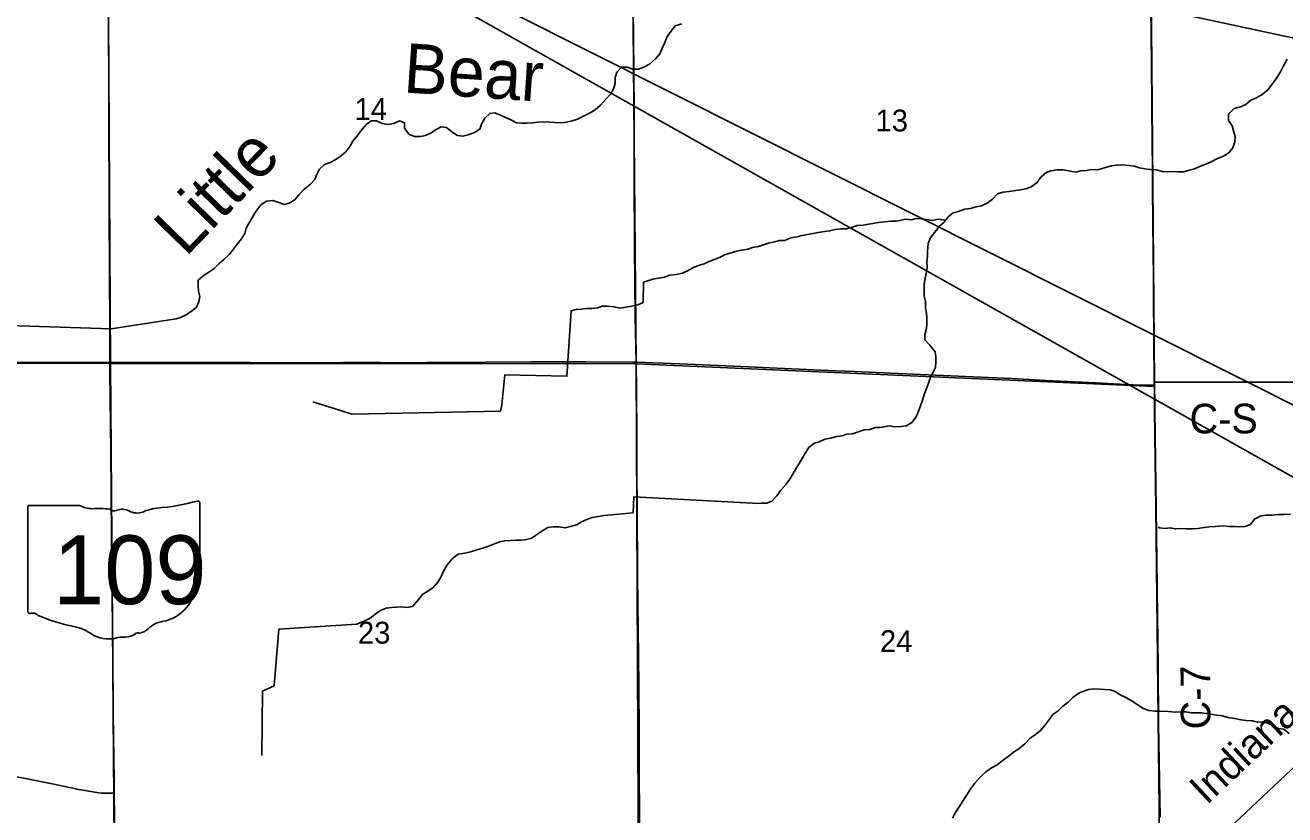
# Model space of a CAD drawing. Extents: x 0 to 34, y 0 to 22.
# Drawn here: x 5.327 to 7.743, y 17.786 to 19.3 of the extents above; entities that cross this region are included whole.
import ezdxf

# ---------------------------------------------------------------- set-up
doc = ezdxf.new("R2010")
doc.units = 0
for name, color, linetype in [('Default', 7, 'Continuous'), ('GM_X_County_Road', 7, 'Continuous'), ('GM_X_County_Road_Text', 7, 'Continuous'), ('GM_X_Minor_River', 7, 'Continuous'), ('GM_X_Minor_River_Text', 7, 'Continuous'), ('GM_X_Rail_Line', 7, 'Continuous'), ('GM_X_Rail_Line_Text', 7, 'Continuous'), ('GM_X_Section', 7, 'Continuous'), ('GM_X_Section_Text', 7, 'Continuous'), ('GM_X_State_Location', 7, 'Continuous'), ('GM_X_State_Route', 7, 'Continuous'), ('GM_X_State_Shield', 7, 'Continuous'), ('GM_X_Township_Road', 7, 'Continuous'), ('SH_Text', 7, 'Continuous')]:
    doc.layers.add(name, color=color, linetype=linetype)

msp = doc.modelspace()

# ---------------------------------------------------------------- linework, layer by layer
at = {"layer": 'Default'}
for points in [[(7.5032, 17.7822), (7.5006, 17.9615), (7.4999, 18.0704), (7.4982, 18.1668), (7.4976, 18.2228), (7.4963, 18.3254), (7.4931, 18.5618), (7.493, 18.5805), (7.4926, 18.6053), (7.4924, 18.6103), (7.4924, 18.6163), (7.4914, 18.6987), (7.4908, 18.7826), (7.4907, 18.8137), (7.4895, 18.9226), (7.4892, 18.9879), (7.4888, 19.0283), (7.4883, 19.0719), (7.487, 19.2243), (7.4864, 19.2834), (7.4852, 19.3829)], [(7.4852, 19.3829), (7.4864, 19.2834), (7.487, 19.2243), (7.4883, 19.0719), (7.4888, 19.0283), (7.4892, 18.9879), (7.4895, 18.9226), (7.4907, 18.8137), (7.4908, 18.7826), (7.4914, 18.6987), (7.4924, 18.6163), (7.4924, 18.6103), (7.4926, 18.6053), (7.493, 18.5805), (7.4931, 18.5618), (7.4963, 18.3254), (7.4976, 18.2228), (7.4982, 18.1668), (7.4999, 18.0704), (7.5006, 17.9615), (7.5032, 17.7822)]]:
    msp.add_lwpolyline(points, dxfattribs=at)
at = {"layer": 'GM_X_County_Road'}
msp.add_line((7.4927, 18.6097), (7.4927, 18.6157), dxfattribs=at)
for points in [[(7.4927, 18.6157), (7.4917, 18.6981), (7.4911, 18.7821), (7.4909, 18.8132), (7.4898, 18.922), (7.4894, 18.9873), (7.4891, 19.0278), (7.4886, 19.0713), (7.4872, 19.2237), (7.4867, 19.2828), (7.4854, 19.3824), (7.4845, 19.4477), (7.484, 19.5099), (7.483, 19.5845), (7.4829, 19.602)], [(4.4843, 18.6526), (4.5342, 18.653), (4.7114, 18.6535), (4.9663, 18.6544), (5.1249, 18.6544), (5.1746, 18.6543), (5.2305, 18.654), (5.3611, 18.6537), (5.4896, 18.6535)], [(5.4896, 18.6535), (5.4979, 18.6535), (5.6222, 18.6535), (5.759, 18.6531), (5.8367, 18.6529), (5.9362, 18.6532), (6.0077, 18.6532), (6.0823, 18.653), (6.0978, 18.6531), (6.1258, 18.6536), (6.2968, 18.6549), (6.4025, 18.6548), (6.4927, 18.6543), (6.4986, 18.6541)], [(6.4986, 18.6541), (6.5828, 18.6511), (6.6853, 18.6465), (6.8809, 18.6376), (6.9182, 18.636), (6.9865, 18.633), (7.1449, 18.626), (7.2194, 18.6225), (7.2846, 18.6191), (7.3809, 18.6143), (7.415, 18.6126), (7.4647, 18.6102), (7.4927, 18.6097)], [(7.4927, 18.6157), (7.5027, 18.6158), (7.5276, 18.6159), (7.935, 18.6156), (8.1215, 18.6157), (8.2739, 18.615), (8.5444, 18.6148), (8.6355, 18.6158)], [(7.5035, 17.7817), (7.5008, 17.961), (7.5001, 18.0698), (7.4985, 18.1663), (7.4978, 18.2222), (7.4965, 18.3249), (7.4934, 18.5613), (7.4932, 18.5799), (7.4928, 18.6048), (7.4927, 18.6097)]]:
    msp.add_lwpolyline(points, dxfattribs=at)
at = {"layer": 'GM_X_Minor_River'}
msp.add_line((6.5127, 18.8074), (6.5123, 18.7683), dxfattribs=at)
for points in [[(6.5862, 19.3023), (6.5737, 19.2987), (6.5652, 19.2881), (6.5579, 19.2768), (6.554, 19.2666), (6.549, 19.2556), (6.5443, 19.2451), (6.5358, 19.2353), (6.5247, 19.2255), (6.5133, 19.2192), (6.5034, 19.2159), (6.4917, 19.2156), (6.4815, 19.2195), (6.4709, 19.2196), (6.4617, 19.2098), (6.4589, 19.2), (6.4584, 19.189), (6.4564, 19.1791), (6.4506, 19.1682), (6.441, 19.1584), (6.4303, 19.1468), (6.4203, 19.1374), (6.4108, 19.1318), (6.3864, 19.1199), (6.3761, 19.1165), (6.3651, 19.114), (6.3552, 19.113), (6.3435, 19.1135), (6.3336, 19.1139), (6.3204, 19.1144), (6.3105, 19.1142), (6.2999, 19.1127), (6.29, 19.1121), (6.2794, 19.1122), (6.2696, 19.113), (6.2586, 19.1188), (6.2484, 19.1231), (6.2386, 19.1278), (6.2281, 19.1317), (6.2182, 19.131), (6.2086, 19.1216), (6.2024, 19.1103), (6.1989, 19.1005), (6.1886, 19.0941), (6.1768, 19.0897), (6.1666, 19.0871), (6.156, 19.0887), (6.1454, 19.0957), (6.1349, 19.1038), (6.1247, 19.1054), (6.1151, 19.0998), (6.1044, 19.0927), (6.0949, 19.0886), (6.0851, 19.0868), (6.0741, 19.0869), (6.0631, 19.0912), (6.0549, 19.1023), (6.0546, 19.1125), (6.0448, 19.1164), (6.0345, 19.1116), (6.0227, 19.1094), (6.0121, 19.1114), (6.0008, 19.1165), (5.991, 19.1166), (5.9814, 19.1095), (5.9722, 19.0985), (5.9645, 19.0887), (5.9557, 19.0778), (5.9499, 19.0673), (5.9422, 19.0575), (5.9315, 19.0481), (5.9216, 19.0421), (5.912, 19.0365), (5.9014, 19.0332), (5.8918, 19.0242), (5.8868, 19.0144), (5.8829, 19.0042), (5.8737, 18.9944), (5.8618, 18.985), (5.8526, 18.9752)], [(7.7473, 19.2347), (7.7407, 19.2234), (7.7348, 19.2106), (7.7267, 19.1985), (7.7183, 19.1872), (7.7102, 19.1759), (7.6995, 19.1673), (7.6872, 19.1602), (7.6777, 19.1565), (7.6682, 19.1479), (7.6579, 19.1435), (7.6457, 19.1402), (7.635, 19.1293), (7.6348, 19.1175), (7.6415, 19.1072), (7.6444, 19.0977), (7.6477, 19.0863), (7.6468, 19.0764), (7.6433, 19.0651), (7.6356, 19.0553), (7.6238, 19.0482), (7.6127, 19.0438), (7.6017, 19.0382), (7.5914, 19.0338), (7.5811, 19.0297), (7.5697, 19.0245), (7.5594, 19.0223), (7.5488, 19.0187), (7.5389, 19.0188), (7.5291, 19.0192), (7.5177, 19.019), (7.5078, 19.0198), (7.4965, 19.023)], [(7.3843, 19.023), (7.3725, 19.0231), (7.3619, 19.0217), (7.3513, 19.0211), (7.3418, 19.0185), (7.3285, 19.0209), (7.3176, 19.0229), (7.3062, 19.023), (7.2948, 19.0209), (7.2853, 19.0179), (7.275, 19.0086), (7.2676, 18.9984), (7.2562, 18.9898), (7.2459, 18.9861), (7.2364, 18.9843), (7.2265, 18.9828), (7.2144, 18.9814), (7.2019, 18.9801), (7.192, 18.9767), (7.1824, 18.9666), (7.1717, 18.9587), (7.1614, 18.9539), (7.1511, 18.9517), (7.1394, 18.9484), (7.1291, 18.947), (7.1173, 18.9429), (7.107, 18.94), (7.0971, 18.9325), (7.0894, 18.9223), (7.0799, 18.9141), (7.0718, 18.9035), (7.0629, 18.8919), (7.0587, 18.8809), (7.0577, 18.8665), (7.0576, 18.857), (7.0564, 18.8464), (7.0567, 18.8354), (7.055, 18.824), (7.0522, 18.8119), (7.0514, 18.802), (7.0509, 18.7903), (7.0515, 18.7808), (7.0537, 18.7701), (7.0536, 18.758), (7.0554, 18.7481), (7.0564, 18.7382), (7.0563, 18.7283), (7.0554, 18.7185), (7.0523, 18.7064), (7.0526, 18.6969), (7.0619, 18.6865), (7.072, 18.6739), (7.0738, 18.664), (7.0733, 18.6538), (7.0728, 18.6439), (7.0624, 18.6235), (7.0593, 18.6137), (7.0554, 18.6035), (7.0515, 18.5921), (7.0483, 18.5815), (7.0444, 18.5702), (7.0401, 18.56), (7.0358, 18.5494), (7.0274, 18.5385), (7.0175, 18.5321), (7.0065, 18.5307), (6.9943, 18.5304), (6.9845, 18.5317), (6.967, 18.5288), (6.9575, 18.5285), (6.9469, 18.5248), (6.9359, 18.5242), (6.9138, 18.5168), (6.9028, 18.5158), (6.8933, 18.5128), (6.8834, 18.5114), (6.8716, 18.5081), (6.8606, 18.5063), (6.85, 18.5011), (6.8397, 18.4982), (6.8301, 18.4903), (6.8224, 18.4786), (6.8132, 18.4628), (6.8066, 18.4515), (6.8008, 18.4417), (6.7935, 18.43), (6.7862, 18.4198), (6.7766, 18.4085), (6.7689, 18.3979), (6.7589, 18.3878), (6.7494, 18.3837), (6.7391, 18.3838), (6.7295, 18.3831), (6.7217, 18.3836)], [(7.4965, 19.023), (7.4855, 19.0235), (7.4746, 19.0244), (7.4643, 19.0264), (7.4545, 19.0295), (7.4443, 19.0307), (7.4318, 19.032), (7.4201, 19.0318), (7.4106, 19.0303), (7.4011, 19.0278), (7.3843, 19.023)], [(5.8526, 18.9752), (5.8442, 18.9654), (5.8335, 18.9587), (5.8236, 18.9565), (5.8134, 18.9604), (5.8025, 18.964), (5.7899, 18.9629), (5.7792, 18.9555), (5.7693, 18.943), (5.7635, 18.9317), (5.7569, 18.9208), (5.7511, 18.9106), (5.7483, 18.9007), (5.7422, 18.8902), (5.7341, 18.88), (5.726, 18.8702), (5.7183, 18.8604), (5.708, 18.851), (5.6984, 18.8428), (5.6892, 18.833), (5.6797, 18.8263), (5.6686, 18.8195), (5.6591, 18.8109), (5.6589, 18.8003), (5.6596, 18.79), (5.6621, 18.7801), (5.6601, 18.7699), (5.6555, 18.7593), (5.6455, 18.7511), (5.6345, 18.744), (5.6249, 18.7395), (5.617, 18.7373)], [(7.0923, 18.9262), (7.0781, 18.9281), (7.0667, 18.9256), (7.0554, 18.9272), (7.0455, 18.9288), (7.0357, 18.9297), (7.0262, 18.9271), (7.0159, 18.928), (6.9973, 18.924), (6.9875, 18.9245), (6.9639, 18.9217), (6.9449, 18.9188), (6.9343, 18.9167), (6.9229, 18.916), (6.9119, 18.912), (6.9024, 18.9098), (6.8906, 18.9095), (6.8808, 18.9085), (6.8697, 18.9055), (6.8599, 18.9045), (6.8485, 18.9027), (6.8375, 18.9006), (6.8276, 18.8988), (6.8173, 18.897), (6.8067, 18.8944), (6.7953, 18.8922), (6.7839, 18.8874), (6.774, 18.8875), (6.7641, 18.8846), (6.7527, 18.8824), (6.7432, 18.8787), (6.7337, 18.8758), (6.7223, 18.8736), (6.7128, 18.8707), (6.7014, 18.8689), (6.6919, 18.8667), (6.6809, 18.8638), (6.6699, 18.8601), (6.6603, 18.8556), (6.6501, 18.8512), (6.6386, 18.8467), (6.6291, 18.8427), (6.6185, 18.8393), (6.6074, 18.8349), (6.5971, 18.8293), (6.5876, 18.8245), (6.5758, 18.8219), (6.5637, 18.8209), (6.553, 18.8172), (6.5416, 18.8151), (6.5306, 18.8133), (6.5211, 18.8099), (6.5127, 18.8074)], [(6.5123, 18.7683), (6.502, 18.7638), (6.4907, 18.7613), (6.4679, 18.7577), (6.4565, 18.7601), (6.4436, 18.7614), (6.4342, 18.7611), (6.4247, 18.7585), (6.4148, 18.7571), (6.4045, 18.7568), (6.3935, 18.7554), (6.3837, 18.7548), (6.3742, 18.7526), (6.3749, 18.7526)], [(6.3742, 18.7526), (6.366, 18.627), (6.247, 18.6297), (6.2415, 18.5721), (6.2387, 18.56), (5.9543, 18.5541), (5.8791, 18.5783)], [(5.617, 18.7373), (5.4924, 18.718), (5.1972, 18.7274), (5.1198, 18.7229)], [(6.7217, 18.3836), (6.4947, 18.3961), (6.4929, 18.3654), (6.4375, 18.3599)], [(6.4375, 18.3599), (6.4147, 18.3563), (6.4044, 18.3526), (6.3942, 18.3482), (6.3846, 18.3422), (6.3728, 18.3389), (6.3629, 18.3363), (6.3512, 18.3387), (6.3406, 18.3381), (6.3296, 18.337), (6.3181, 18.3299), (6.3082, 18.3236), (6.2987, 18.3168), (6.2888, 18.3143), (6.2793, 18.3129), (6.2691, 18.313), (6.2577, 18.3119), (6.247, 18.3117), (6.2372, 18.3099), (6.2254, 18.305), (6.2143, 18.3006), (6.2041, 18.2973), (6.1915, 18.294), (6.1812, 18.2907), (6.1698, 18.2881), (6.1573, 18.286), (6.1466, 18.2774), (6.1366, 18.2653), (6.1289, 18.2521), (6.1246, 18.2419), (6.1188, 18.2321), (6.1096, 18.2223), (6.0993, 18.2148), (6.0898, 18.2096), (6.079, 18.1957), (6.0698, 18.1855), (6.0592, 18.1841), (6.0493, 18.1853), (6.0394, 18.1847), (6.03, 18.184), (6.0197, 18.1826), (6.0087, 18.1782), (5.9984, 18.1711), (5.988, 18.1624), (5.9633, 18.1517)], [(7.7539, 18.3624), (7.7414, 18.3621), (7.7304, 18.3619), (7.7186, 18.3608), (7.7072, 18.3606), (7.6966, 18.3596), (7.6844, 18.3532), (7.6767, 18.3427), (7.6661, 18.339), (7.6558, 18.3387), (7.6456, 18.3392), (7.6357, 18.3389), (7.6248, 18.3406), (7.6092, 18.3388), (7.5979, 18.3386), (7.588, 18.3372), (7.5758, 18.335), (7.566, 18.3347), (7.5535, 18.3345), (7.5429, 18.3354), (7.533, 18.3343), (7.5228, 18.3363), (7.5126, 18.3349), (7.5027, 18.3365), (7.4997, 18.3377)], [(5.9633, 18.1517), (5.8134, 18.1422), (5.8046, 18.0337), (5.7825, 18.0233), (5.7812, 17.9003)], [(7.3663, 18.0265), (7.3585, 18.0243), (7.3475, 18.0199), (7.3372, 18.012), (7.3276, 18.0022), (7.3169, 17.9944), (7.3073, 17.985), (7.2978, 17.9786), (7.2897, 17.9669), (7.282, 17.9571), (7.2739, 17.9473), (7.2644, 17.9402), (7.2537, 17.9327), (7.2441, 17.9226), (7.2334, 17.9136), (7.2219, 17.9057), (7.2123, 17.8979), (7.2009, 17.8896), (7.1909, 17.8825), (7.1803, 17.8762), (7.1692, 17.8687), (7.1592, 17.8593), (7.1481, 17.8469), (7.1408, 17.8367), (7.1331, 17.8247), (7.1257, 17.8137), (7.1184, 17.8017), (7.1107, 17.79), (7.1056, 17.7798)], [(7.7514, 17.9424), (7.7409, 17.9505), (7.7307, 17.9521), (7.7209, 17.9571), (7.7103, 17.9618), (7.7005, 17.9646), (7.6907, 17.9643), (7.6808, 17.9663), (7.6687, 17.9675), (7.6589, 17.9684), (7.6468, 17.9712), (7.6336, 17.9732), (7.623, 17.976), (7.6124, 17.9776), (7.5927, 17.9809), (7.5829, 17.9817), (7.5632, 17.9819), (7.553, 17.9836), (7.5431, 17.9837), (7.5333, 17.9834), (7.5197, 17.9843), (7.5037, 17.9848), (7.4939, 17.9849), (7.4822, 17.9866), (7.4712, 17.9905), (7.4607, 17.997), (7.4498, 18.004), (7.4389, 18.0105), (7.4272, 18.0164), (7.4174, 18.0225), (7.4076, 18.0261), (7.3978, 18.0269), (7.3876, 18.027), (7.377, 18.0279), (7.3663, 18.0265), (7.3659, 18.0265)]]:
    msp.add_lwpolyline(points, dxfattribs=at)
at = {"layer": 'GM_X_Rail_Line'}
msp.add_lwpolyline([(5.6036, 14.1), (5.6231, 15.2124), (5.6254, 15.4429), (5.6392, 15.5731), (5.6554, 15.6619), (5.6784, 15.7322), (5.7095, 15.8198), (5.7429, 15.8889), (5.7752, 15.9442), (5.8121, 16.0007), (5.8512, 16.0606), (5.9042, 16.1217), (5.9987, 16.2174), (6.5299, 16.7153), (7.3509, 17.4922), (8.0819, 18.1807), (8.7161, 18.7707), (8.9, 18.9438)], dxfattribs=at)
at = {"layer": 'GM_X_Section'}
for points in [[(4.4763, 19.663), (5.485, 19.653), (5.4908, 18.6512), (4.4846, 18.6535)], [(5.485, 19.653), (6.4898, 19.6568), (6.4992, 18.6508), (5.4908, 18.6512)], [(6.4898, 19.6568), (7.4844, 19.6018), (7.4927, 18.6151), (7.4929, 18.6076), (6.4992, 18.6508)], [(7.4843, 19.6166), (8.626, 19.6083), (8.6395, 18.6159), (7.4927, 18.6151), (7.4844, 19.6018)], [(4.4846, 18.6535), (5.4908, 18.6512), (5.4987, 17.6483), (4.4933, 17.6509)], [(5.4908, 18.6512), (6.4992, 18.6508), (6.5031, 17.6487), (5.4987, 17.6483)], [(6.4992, 18.6508), (7.4929, 18.6076), (7.5039, 17.6243), (7.5038, 17.6183), (6.5031, 17.6487)], [(7.4927, 18.6151), (8.6395, 18.6159), (8.6491, 17.6213), (7.5039, 17.6243), (7.4929, 18.6076)]]:
    msp.add_lwpolyline(points, close=True, dxfattribs=at)
at = {"layer": 'GM_X_State_Route'}
msp.add_lwpolyline([(5.4994, 17.652), (5.4992, 17.672), (5.4983, 17.787), (5.4981, 17.8181), (5.4981, 17.828), (5.4981, 17.8523), (5.4963, 17.9797), (5.4953, 18.0979), (5.494, 18.2004), (5.4935, 18.2378), (5.4913, 18.4833), (5.4897, 18.6357), (5.4896, 18.6535), (5.4893, 18.6854), (5.4887, 18.8626), (5.4886, 18.9093), (5.4885, 18.9621), (5.4881, 19.0056), (5.4877, 19.0709), (5.4874, 19.1734), (5.4864, 19.4408)], dxfattribs=at)
at = {"layer": 'GM_X_State_Shield'}
for p, q in [((5.662, 18.2799), (5.662, 18.3846)), ((5.3325, 18.3761), (5.3325, 18.176)), ((5.4322, 18.3796), (5.3357, 18.3796)), ((5.662, 18.2799), (5.662, 18.2799))]:
    msp.add_line(p, q, dxfattribs=at)
for centre, major_axis, start_param, end_param in [((5.5446, 18.6524), (0.3495, 0), 4.814394, 5.042369), ((5.6584, 18.385), (0.00367, 0), 6.141152, 7.989035), ((5.3362, 18.3766), (0.00382, 0), 1.712693, 3.28349), ((5.4552, 18.4028), (0.037, 0), 4.042523, 4.731795), ((5.4675, 18.2672), (0.133, 0), 1.404758, 1.657858), ((5.4977, 18.3776), (0.0107, 0), 3.836095, 5.185415), ((5.5134, 18.3545), (0.0222, 0), 0.950623, 2.079405), ((5.542, 18.3862), (0.0267, 0), 4.081561, 5.145723), ((5.5892, 18.3185), (0.0703, 0), 1.699011, 2.107814), ((5.6612, 18.2722), (0.00568, 0), 1.883978, 3.671073), ((5.6251, 18.2589), (0.0341, 0), 5.934695, 6.695948), ((5.6581, 18.2795), (0.00393, 0), 5.05454, 6.418171), ((5.6752, 18.2361), (0.0248, 0), 2.387724, 3.262537), ((5.5642, 18.2227), (0.0874, 0), 5.101752, 6.440018), ((5.3363, 18.1756), (0.00385, 0), 3.00124, 4.508301), ((5.3368, 18.1961), (0.0294, 0), 4.665946, 4.897461), ((5.3429, 18.1645), (0.0106, 0), 0.519207, 1.627899), ((5.4767, 18.3443), (0.2524, 0), 4.195997, 4.488961), ((5.4014, 18.0861), (0.079, 0), 0.823519, 1.323587), ((5.5404, 18.1566), (0.0282, 0), 4.937069, 5.64225), ((5.6011, 18.1198), (0.0479, 0), 1.647645, 2.488434), ((5.4869, 18.1635), (0.0501, 0), 4.026481, 4.996735), ((5.5158, 18.0943), (0.0412, 0), 1.495662, 1.94098), ((5.5195, 18.1485), (0.0267, 0), 4.691044, 5.507374), ((5.5436, 18.1291), (0.00752, 0), 1.147584, 2.315152)]:
    msp.add_ellipse(centre, major_axis=major_axis, ratio=0.8, start_param=start_param, end_param=end_param, dxfattribs=at)
at = {"layer": 'GM_X_Township_Road'}
for points in [[(6.4986, 18.6541), (6.497, 18.743), (6.4962, 18.8052), (6.4957, 18.8798), (6.4957, 18.8975), (6.4953, 18.9862), (6.495, 19.1012), (6.4948, 19.1323), (6.4942, 19.2131), (6.4931, 19.3311), (6.4919, 19.4276), (6.4911, 19.5536), (6.4905, 19.6282), (6.4906, 19.6548)], [(6.5059, 17.6525), (6.5054, 17.6677), (6.5051, 17.7796), (6.5047, 17.8728), (6.5046, 17.9008), (6.5044, 17.9443), (6.5042, 18.0344), (6.5029, 18.1432), (6.502, 18.1898), (6.5016, 18.2458), (6.5011, 18.3763), (6.5004, 18.4416), (6.5, 18.5131), (6.4994, 18.6001), (6.4986, 18.6529), (6.4986, 18.6541)], [(4.991, 17.9191), (5.0068, 17.9165), (5.0238, 17.9131), (5.0601, 17.9065), (5.1001, 17.8993), (5.1258, 17.8944), (5.1612, 17.8881), (5.2531, 17.8708), (5.382, 17.8453), (5.4122, 17.8389), (5.4184, 17.8375), (5.4244, 17.8362), (5.4291, 17.8352), (5.4345, 17.8343), (5.4611, 17.8299), (5.4729, 17.8282), (5.475, 17.8281), (5.4773, 17.8279), (5.4799, 17.8277), (5.4869, 17.8279), (5.4917, 17.828), (5.4981, 17.828)]]:
    msp.add_lwpolyline(points, dxfattribs=at)
at = {"layer": 'SH_Text'}
for points in [[(5.4846, 19.763), (9.956, 18.8047), (9.956, 19.0851)], [(5.4846, 19.7138), (9.956, 17.197), (9.956, 17.4693)]]:
    msp.add_lwpolyline(points, close=True, dxfattribs=at)

# ---------------------------------------------------------------- texts
at = {"layer": 'GM_X_County_Road_Text'}
for s, rotation, p in [('C-S', 0, (7.56, 18.5175)), ('C-7', 90.4581, (7.6004, 17.9503))]:
    msp.add_text(s, height=0.05682, rotation=rotation, dxfattribs=at).set_placement(p)
at = {"layer": 'GM_X_Minor_River_Text'}
for s, height, rotation, p in [('Bear', 0.09476, 356.1302, (6.051, 19.1712)), ('Little', 0.09475, 45.8125, (5.6346, 18.8541))]:
    msp.add_text(s, height=height, rotation=rotation, dxfattribs=at).set_placement(p)
at = {"layer": 'GM_X_Rail_Line_Text'}
msp.add_text('Indiana & Ohio Railway', height=0.056629, rotation=43.1881, dxfattribs=at).set_placement((7.5929, 17.8042))
at = {"layer": 'GM_X_Section_Text'}
for s, p in [('14', (5.9588, 19.1183)), ('13', (6.9579, 19.0963)), ('23', (5.9654, 18.1146)), ('24', (6.9663, 18.0983))]:
    msp.add_text(s, height=0.04186, rotation=0, dxfattribs=at).set_placement(p)
at = {"layer": 'GM_X_State_Location'}
for s in ['s', 'r']:
    msp.add_text(s, height=0.000189, dxfattribs=at).set_placement((5.4935, 18.2628))
msp.add_text('109', height=0.000189, rotation=0, dxfattribs=at).set_placement((5.4267, 18.249))
at = {"layer": 'GM_X_State_Shield'}
msp.add_text('109', height=0.13184, dxfattribs=at).set_placement((5.3809, 18.1901))

doc.saveas('drawing.dxf')
